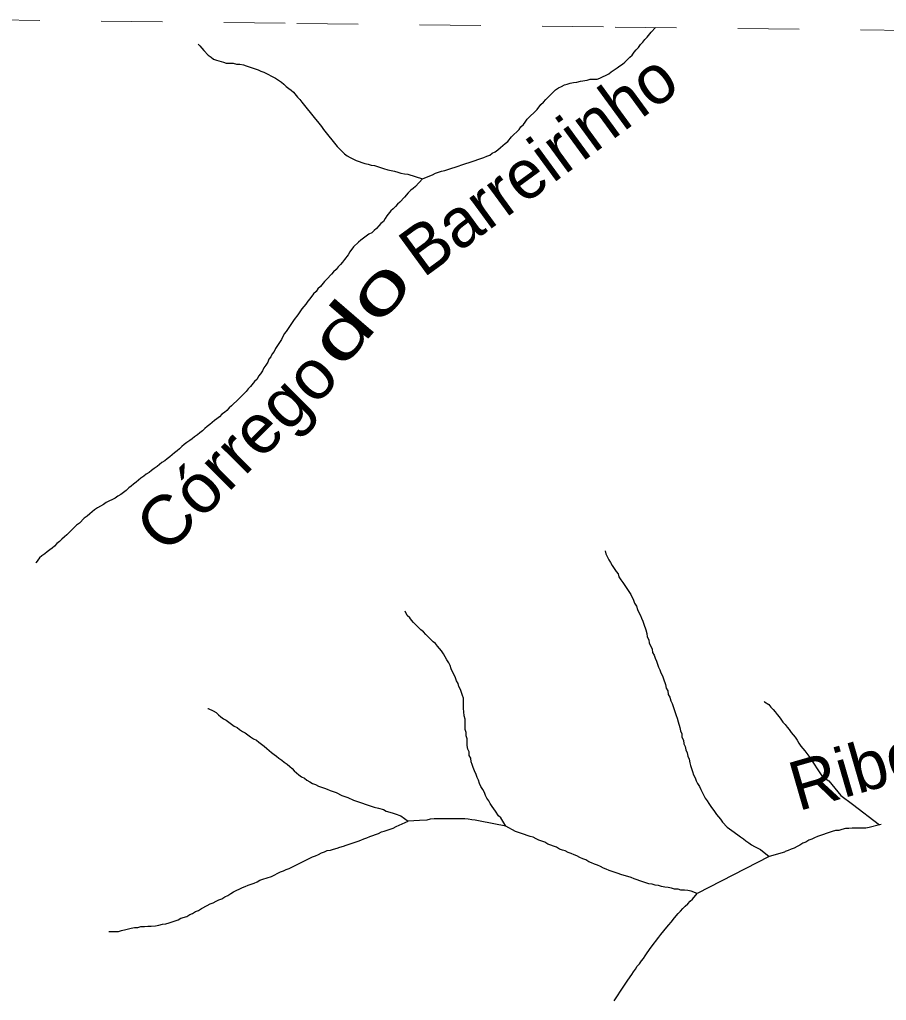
# Model space of a CAD drawing. Extents: x 652.3 to 678, y 7316.9 to 7344.9.
# Drawn here: x 666.148 to 667.562, y 7343.176 to 7344.776 of the extents above; entities that cross this region are included whole.
import ezdxf
from ezdxf.enums import TextEntityAlignment as Align

# ---------------------------------------------------------------- set-up
doc = ezdxf.new("R2010")
doc.units = 0
doc.header["$LTSCALE"] = 0.032
doc.linetypes.add('SHORT_DASHED', pattern=[2.7, 1.5, -1.2])
doc.layers.add('53', color=7, linetype='SHORT_DASHED', lineweight=13)
doc.layers.add('7', color=7, linetype='Continuous', lineweight=25)
doc.layers.add('61', color=7, linetype='Continuous')

msp = doc.modelspace()

# ---------------------------------------------------------------- linework, layer by layer
at = {"layer": '53'}
msp.add_lwpolyline([(666.0809, 7344.7756), (666.6, 7344.7695), (667.1191, 7344.7635), (667.6382, 7344.7574), (668.1573, 7344.7513), (668.6764, 7344.7452), (669.1955, 7344.7391), (669.7146, 7344.733), (670.2337, 7344.7268), (670.7528, 7344.7206), (671.2719, 7344.7144), (671.791, 7344.7082), (672.3102, 7344.702), (672.8293, 7344.6957), (673.3484, 7344.6895), (673.8675, 7344.6832), (674.3866, 7344.6769), (674.9057, 7344.6705), (675.4248, 7344.6642), (675.9439, 7344.6578), (676.4631, 7344.6514), (676.9822, 7344.645), (677.5013, 7344.6386), (678.0204, 7344.6322)], dxfattribs=at)
at = {"layer": '7'}
msp.add_line((667.5529, 7343.4632), (667.5503, 7343.4627), dxfattribs=at)
for points in [[(666.8047, 7344.5162), (666.8166, 7344.521), (666.8214, 7344.5226), (666.8262, 7344.525), (666.831, 7344.5266), (666.8357, 7344.5282), (666.8413, 7344.5298), (666.8493, 7344.5322), (666.8612, 7344.5361), (666.8708, 7344.5393), (666.8755, 7344.5409), (666.8811, 7344.5425), (666.8906, 7344.5457), (666.8954, 7344.5473), (666.905, 7344.5505), (666.9097, 7344.5528), (666.9145, 7344.5544), (666.9185, 7344.5576), (666.9233, 7344.56), (666.928, 7344.5632), (666.932, 7344.5672), (666.936, 7344.5704), (666.94, 7344.5735), (666.944, 7344.5767), (666.9503, 7344.5847), (666.9623, 7344.5966), (666.9654, 7344.6006), (666.9694, 7344.6046), (666.9726, 7344.6085), (666.9758, 7344.6133), (666.9917, 7344.6292), (666.9981, 7344.6372), (667.002, 7344.6412), (667.006, 7344.6451), (667.0219, 7344.6611), (667.0267, 7344.6642), (667.0315, 7344.6666), (667.0363, 7344.669), (667.041, 7344.6706), (667.0458, 7344.6722), (667.0514, 7344.673), (667.0569, 7344.6738), (667.0625, 7344.6754), (667.0737, 7344.677), (667.0784, 7344.6786), (667.0896, 7344.6786), (667.0943, 7344.6802), (667.1087, 7344.6873), (667.1126, 7344.6905), (667.1174, 7344.6937), (667.1222, 7344.6969), (667.127, 7344.7001), (667.1309, 7344.7032), (667.1349, 7344.7064), (667.1429, 7344.7144), (667.1469, 7344.7176), (667.15, 7344.7223), (667.1532, 7344.7263), (667.1572, 7344.7303), (667.1604, 7344.7351), (667.1644, 7344.739), (667.1675, 7344.743), (667.1715, 7344.747), (667.1779, 7344.755), (667.1851, 7344.7627)], [(666.4392, 7344.7353), (666.4419, 7344.7326), (666.4482, 7344.7255), (666.4554, 7344.7176), (666.4602, 7344.7144), (666.4642, 7344.7112), (666.4689, 7344.7096), (666.4801, 7344.7064), (666.4848, 7344.7048), (666.496, 7344.7048), (666.5016, 7344.7032), (666.5071, 7344.7032), (666.5127, 7344.7016), (666.5175, 7344.7001), (666.5222, 7344.6985), (666.5366, 7344.6937), (666.5413, 7344.6913), (666.5461, 7344.6897), (666.5652, 7344.6802), (666.57, 7344.677), (666.5748, 7344.6738), (666.5787, 7344.6706), (666.5827, 7344.6666), (666.5867, 7344.6634), (666.5907, 7344.6603), (666.5946, 7344.6571), (666.601, 7344.6491), (666.605, 7344.6451), (666.6082, 7344.6412), (666.6305, 7344.6133), (666.6336, 7344.6093), (666.64, 7344.6014), (666.6432, 7344.5966), (666.6655, 7344.5688), (666.6694, 7344.5648), (666.6774, 7344.5568), (666.6822, 7344.5536), (666.6869, 7344.5505), (666.6965, 7344.5457), (666.7108, 7344.5409), (666.7164, 7344.5401), (666.7212, 7344.5385), (666.7267, 7344.5377), (666.7363, 7344.5345), (666.7411, 7344.533), (666.7482, 7344.5306), (666.7594, 7344.5282), (666.7649, 7344.5266), (666.7697, 7344.525), (666.7753, 7344.5242), (666.7808, 7344.5234), (666.8047, 7344.5162)], [(666.8047, 7344.5162), (666.7936, 7344.5035), (666.7896, 7344.5003), (666.7856, 7344.4972), (666.7816, 7344.4932), (666.7753, 7344.486), (666.7681, 7344.4781), (666.7641, 7344.4749), (666.7609, 7344.4709), (666.757, 7344.4669), (666.753, 7344.4637), (666.7466, 7344.4558), (666.7442, 7344.451), (666.7411, 7344.4462), (666.7371, 7344.443), (666.7339, 7344.4391), (666.7299, 7344.4351), (666.7259, 7344.4319), (666.722, 7344.4279), (666.7172, 7344.4255), (666.7132, 7344.4224), (666.7084, 7344.4192), (666.7045, 7344.416), (666.7005, 7344.4128), (666.6925, 7344.4049), (666.6862, 7344.3969), (666.6838, 7344.3921), (666.6774, 7344.3842), (666.6742, 7344.3802), (666.671, 7344.3762), (666.6671, 7344.3722), (666.6639, 7344.3682), (666.6599, 7344.3643), (666.6567, 7344.3603), (666.6488, 7344.3523), (666.6448, 7344.3484), (666.6384, 7344.3404), (666.6344, 7344.3364), (666.6313, 7344.3324), (666.6273, 7344.3285), (666.6209, 7344.3205), (666.6177, 7344.3165), (666.6145, 7344.3118), (666.6114, 7344.3078)], [(666.6114, 7344.3078), (666.6082, 7344.3038), (666.605, 7344.299), (666.6018, 7344.2943), (666.5954, 7344.2863), (666.5859, 7344.272), (666.5827, 7344.2672), (666.5795, 7344.2632), (666.5748, 7344.2537), (666.5716, 7344.2489), (666.5684, 7344.2441), (666.5652, 7344.2393), (666.5628, 7344.2346), (666.5596, 7344.2306), (666.5573, 7344.2258), (666.5541, 7344.2218), (666.5525, 7344.2171), (666.5493, 7344.2123), (666.5461, 7344.2075), (666.5437, 7344.2027), (666.5405, 7344.198), (666.5374, 7344.194), (666.535, 7344.1892), (666.531, 7344.1852), (666.5246, 7344.1773), (666.5207, 7344.1733), (666.5175, 7344.1693), (666.5095, 7344.1614), (666.5055, 7344.1574), (666.4936, 7344.1455), (666.4896, 7344.1423), (666.4856, 7344.1383), (666.4817, 7344.1351), (666.4777, 7344.1319), (666.4737, 7344.128), (666.4697, 7344.1248), (666.4657, 7344.1216), (666.4618, 7344.1184), (666.4578, 7344.1152), (666.4538, 7344.112), (666.4498, 7344.1089), (666.4459, 7344.1049), (666.4419, 7344.1017), (666.4379, 7344.0985), (666.4331, 7344.0953), (666.4291, 7344.0921), (666.4252, 7344.089), (666.4204, 7344.0858), (666.4164, 7344.0826), (666.4124, 7344.0794), (666.4085, 7344.0754), (666.4045, 7344.0723), (666.4005, 7344.0691), (666.3965, 7344.0659), (666.3925, 7344.0627), (666.3886, 7344.0595), (666.3846, 7344.0563), (666.3798, 7344.0532), (666.3758, 7344.05), (666.3719, 7344.0468), (666.3671, 7344.0436), (666.3631, 7344.0404), (666.3591, 7344.0372), (666.3544, 7344.0341), (666.3504, 7344.0309), (666.3456, 7344.0277), (666.3416, 7344.0245), (666.3376, 7344.0213), (666.3337, 7344.0181), (666.3297, 7344.015), (666.3257, 7344.0118), (666.3217, 7344.0078), (666.317, 7344.0046), (666.313, 7344.0014), (666.3082, 7343.9983), (666.3034, 7343.9951), (666.2891, 7343.9879), (666.2843, 7343.9847), (666.2796, 7343.9823), (666.2748, 7343.9792), (666.27, 7343.976), (666.266, 7343.9728), (666.2621, 7343.9696), (666.2581, 7343.9656), (666.2533, 7343.9624), (666.2453, 7343.9545), (666.2406, 7343.9513), (666.2247, 7343.9354), (666.2207, 7343.9322), (666.2167, 7343.9282), (666.2127, 7343.9243), (666.2087, 7343.9211), (666.2048, 7343.9171), (666.2008, 7343.9139), (666.1968, 7343.9107), (666.1928, 7343.9075), (666.1888, 7343.9044), (666.1841, 7343.9012), (666.1801, 7343.898), (666.1745, 7343.89), (666.1743, 7343.8897)], [(667.103, 7343.9095), (667.1031, 7343.9091), (667.1039, 7343.9044), (667.1087, 7343.8948), (667.1118, 7343.89), (667.1142, 7343.8853), (667.1206, 7343.8757), (667.1238, 7343.8717), (667.1254, 7343.867), (667.1286, 7343.8622), (667.1317, 7343.8574), (667.1413, 7343.8431), (667.1445, 7343.8383), (667.1492, 7343.8288), (667.1508, 7343.824), (667.154, 7343.8192), (667.1556, 7343.8137), (667.158, 7343.8089), (667.1604, 7343.8041), (667.162, 7343.7993), (667.1644, 7343.7946), (667.166, 7343.7898), (667.1691, 7343.7802), (667.1707, 7343.7747), (667.1715, 7343.7691), (667.1739, 7343.7643), (667.1747, 7343.7588), (667.1771, 7343.754), (667.1795, 7343.7492), (667.1803, 7343.7436), (667.1827, 7343.7389), (667.1843, 7343.7341), (667.1866, 7343.7293), (667.1882, 7343.7245), (667.1898, 7343.7198), (667.1922, 7343.715), (667.1938, 7343.7102), (667.1962, 7343.7054), (667.1978, 7343.7007), (667.201, 7343.6911), (667.2026, 7343.6855), (667.2049, 7343.6808), (667.2057, 7343.6752), (667.2081, 7343.6704), (667.2097, 7343.6649), (667.2121, 7343.6601), (667.2169, 7343.6458), (667.2185, 7343.641), (667.2201, 7343.6362), (667.2217, 7343.6306), (667.2248, 7343.6211), (667.2256, 7343.6155), (667.228, 7343.6108), (667.228, 7343.6052), (667.2304, 7343.6004), (667.2312, 7343.5948), (667.2336, 7343.5901), (667.2344, 7343.5845), (667.2368, 7343.5797), (667.2376, 7343.5742), (667.24, 7343.5694), (667.2407, 7343.5638), (667.2423, 7343.559), (667.2439, 7343.5543), (667.2455, 7343.5495), (667.2471, 7343.5439), (667.2495, 7343.5391), (667.2511, 7343.5344), (667.2535, 7343.5296), (667.2567, 7343.5248), (667.259, 7343.52), (667.2662, 7343.5057), (667.2694, 7343.5017), (667.2718, 7343.497), (667.275, 7343.4922), (667.2813, 7343.4842), (667.2845, 7343.4795), (667.2909, 7343.4715), (667.2941, 7343.4667), (667.302, 7343.4588), (667.3092, 7343.4532), (667.3195, 7343.446), (667.3235, 7343.4429), (667.3283, 7343.4397), (667.3323, 7343.4365), (667.337, 7343.4333), (667.3418, 7343.4301), (667.3466, 7343.4269), (667.3561, 7343.4222), (667.3704, 7343.411)], [(666.9408, 7343.4604), (666.9328, 7343.4739), (666.9288, 7343.4771), (666.9241, 7343.485), (666.9185, 7343.4922), (666.9153, 7343.497), (666.9129, 7343.5017), (666.9097, 7343.5057), (666.9074, 7343.5105), (666.9058, 7343.5153), (666.9034, 7343.52), (666.9002, 7343.5248), (666.8978, 7343.5296), (666.8962, 7343.5352), (666.8938, 7343.5399), (666.8922, 7343.5447), (666.8899, 7343.5503), (666.8875, 7343.5559), (666.8859, 7343.5606), (666.8843, 7343.5654), (666.8835, 7343.571), (666.8811, 7343.5757), (666.8811, 7343.5813), (666.8787, 7343.5861), (666.8779, 7343.5917), (666.8779, 7343.6028), (666.8763, 7343.6076), (666.8763, 7343.6131), (666.8747, 7343.6179), (666.8747, 7343.6346), (666.8731, 7343.6402), (666.8723, 7343.6466), (666.8715, 7343.6521), (666.8715, 7343.6688), (666.87, 7343.6736), (666.8668, 7343.6832), (666.8644, 7343.6879), (666.8628, 7343.6927), (666.8604, 7343.6975), (666.8588, 7343.7023), (666.8564, 7343.707), (666.854, 7343.7118), (666.8517, 7343.7166), (666.8501, 7343.7222), (666.8477, 7343.7269), (666.8445, 7343.7317), (666.8421, 7343.7365), (666.8389, 7343.7412), (666.8357, 7343.746), (666.8294, 7343.754), (666.8262, 7343.758), (666.8222, 7343.7611), (666.8103, 7343.7731), (666.8063, 7343.7771), (666.8023, 7343.7802), (666.7904, 7343.7922), (666.7872, 7343.7961), (666.784, 7343.8001), (666.78, 7343.8041), (666.7767, 7343.8108)], [(666.455, 7343.6523), (666.4554, 7343.6521), (666.4634, 7343.6482), (666.4681, 7343.6458), (666.4721, 7343.6418), (666.4761, 7343.6386), (666.4801, 7343.6354), (666.4848, 7343.633), (666.4888, 7343.6299), (666.4936, 7343.6267), (666.4976, 7343.6235), (666.5024, 7343.6211), (666.5063, 7343.6179), (666.5111, 7343.6147), (666.5159, 7343.6123), (666.5199, 7343.6092), (666.5246, 7343.606), (666.5294, 7343.6028), (666.5342, 7343.6004), (666.5382, 7343.5972), (666.5421, 7343.594), (666.5469, 7343.5909), (666.5509, 7343.5869), (666.5549, 7343.5837), (666.5588, 7343.5805), (666.5628, 7343.5773), (666.5668, 7343.5742), (666.5708, 7343.571), (666.5756, 7343.5678), (666.5795, 7343.5646), (666.5843, 7343.5614), (666.5883, 7343.5574), (666.5923, 7343.5543), (666.5954, 7343.5503), (666.5994, 7343.5471), (666.6034, 7343.5439), (666.6074, 7343.5407), (666.6122, 7343.5383), (666.6161, 7343.5352), (666.6209, 7343.5328), (666.6257, 7343.5296), (666.6305, 7343.528), (666.6352, 7343.5256), (666.6448, 7343.5224), (666.6496, 7343.5208), (666.6543, 7343.5185), (666.6639, 7343.5153), (666.6734, 7343.5105), (666.683, 7343.5073), (666.6925, 7343.5025), (666.6973, 7343.5009), (666.7021, 7343.4994), (666.7164, 7343.4946), (666.7212, 7343.493), (666.7259, 7343.4914), (666.7331, 7343.4898), (666.7411, 7343.4874), (666.7458, 7343.485), (666.7554, 7343.4819), (666.7602, 7343.4803), (666.7697, 7343.4771), (666.7816, 7343.4683)], [(667.3622, 7343.6635), (667.3625, 7343.6633), (667.3697, 7343.6585), (667.3728, 7343.6545), (667.3768, 7343.6505), (667.38, 7343.6466), (667.3832, 7343.6426), (667.3864, 7343.6386), (667.3895, 7343.6346), (667.3927, 7343.6299), (667.3967, 7343.6259), (667.3999, 7343.6219), (667.4031, 7343.6179), (667.4063, 7343.6131), (667.4094, 7343.6092), (667.4126, 7343.6052), (667.4158, 7343.6004), (667.419, 7343.5956), (667.4222, 7343.5909), (667.4253, 7343.5869), (667.4285, 7343.5829), (667.4349, 7343.5742), (667.4572, 7343.5407), (667.4675, 7343.5344), (667.4874, 7343.5105), (667.5065, 7343.4962), (667.5503, 7343.4627)], [(666.8989, 7343.4682), (666.8962, 7343.4691), (666.8906, 7343.4699), (666.8851, 7343.4707), (666.8795, 7343.4715), (666.8739, 7343.4723), (666.8684, 7343.4723), (666.8628, 7343.4723), (666.8572, 7343.4723), (666.8517, 7343.4723), (666.8461, 7343.4723), (666.8405, 7343.4723), (666.8349, 7343.4723), (666.8294, 7343.4723), (666.8238, 7343.4723), (666.8174, 7343.4715), (666.8119, 7343.4699), (666.8001, 7343.4693)], [(666.2931, 7343.2885), (666.309, 7343.2885), (666.3138, 7343.2901), (666.3209, 7343.2917), (666.3297, 7343.2941), (666.3353, 7343.2949), (666.3408, 7343.2949), (666.3456, 7343.2965), (666.3512, 7343.2965), (666.3567, 7343.2973), (666.3623, 7343.2973), (666.3695, 7343.298), (666.375, 7343.2988), (666.3806, 7343.3004), (666.3862, 7343.3012), (666.3917, 7343.3028), (666.3965, 7343.3044), (666.4013, 7343.306), (666.4061, 7343.3076), (666.4108, 7343.31), (666.4204, 7343.3132), (666.4252, 7343.3163), (666.4299, 7343.3179), (666.4347, 7343.3211), (666.4395, 7343.3227), (666.4443, 7343.3259), (666.4538, 7343.3307), (666.4586, 7343.3339), (666.4634, 7343.3354), (666.4681, 7343.3378), (666.4729, 7343.3402), (666.4777, 7343.3418), (666.4825, 7343.345), (666.4872, 7343.3474), (666.492, 7343.3506), (666.4968, 7343.353), (666.5111, 7343.3601), (666.5159, 7343.3617), (666.5207, 7343.3641), (666.5254, 7343.3657), (666.5302, 7343.3673), (666.535, 7343.3697), (666.5397, 7343.372), (666.5445, 7343.3736), (666.5588, 7343.3784), (666.5732, 7343.3856), (666.5779, 7343.3872), (666.5827, 7343.3896), (666.5875, 7343.3911), (666.6209, 7343.4079), (666.6257, 7343.4102), (666.6305, 7343.4118), (666.6352, 7343.4142), (666.64, 7343.4166), (666.6448, 7343.4182), (666.6496, 7343.4206), (666.6551, 7343.4214), (666.6599, 7343.423), (666.6655, 7343.4246), (666.6702, 7343.4262), (666.6758, 7343.4277), (666.6806, 7343.4293), (666.6854, 7343.4309), (666.6997, 7343.4357), (666.7045, 7343.4373), (666.7092, 7343.4397), (666.714, 7343.4413), (666.7188, 7343.4437), (666.7331, 7343.4484), (666.7379, 7343.4508), (666.7426, 7343.4524), (666.757, 7343.4572), (666.7617, 7343.4596), (666.7816, 7343.4683)], [(666.8001, 7343.4693), (666.7816, 7343.4683), (666.7816, 7343.4683)], [(666.9408, 7343.4604), (666.9408, 7343.4604), (666.8989, 7343.4682)], [(667.2527, 7343.3506), (667.2431, 7343.3545), (667.2376, 7343.3553), (667.232, 7343.3561), (667.2264, 7343.3561), (667.2217, 7343.3577), (667.2161, 7343.3577), (667.2113, 7343.3593), (667.2057, 7343.3601), (667.2002, 7343.3609), (667.1946, 7343.3617), (667.1898, 7343.3633), (667.1843, 7343.3641), (667.1795, 7343.3657), (667.1739, 7343.3665), (667.1691, 7343.3681), (667.1644, 7343.3697), (667.1596, 7343.3713), (667.1548, 7343.3728), (667.15, 7343.3744), (667.1453, 7343.3768), (667.1397, 7343.3784), (667.1341, 7343.38), (667.1286, 7343.3816), (667.1238, 7343.3832), (667.119, 7343.3848), (667.1142, 7343.3864), (667.1095, 7343.388), (667.1047, 7343.3903), (667.0999, 7343.3919), (667.0951, 7343.3943), (667.0904, 7343.3967), (667.0856, 7343.3983), (667.0808, 7343.4007), (667.076, 7343.4023), (667.0713, 7343.4055), (667.0665, 7343.4071), (667.0617, 7343.4094), (667.0569, 7343.4118), (667.0522, 7343.4134), (667.0474, 7343.4158), (667.0426, 7343.4174), (667.0378, 7343.4198), (667.0331, 7343.4214), (667.0283, 7343.423), (667.0235, 7343.4262), (667.0188, 7343.4277), (667.014, 7343.4293), (667.0092, 7343.4309), (667.0044, 7343.4341), (666.9997, 7343.4357), (666.9949, 7343.4373), (666.9901, 7343.4397), (666.9853, 7343.4421), (666.9806, 7343.4437), (666.9758, 7343.4453), (666.971, 7343.4468), (666.9662, 7343.4484), (666.9615, 7343.45), (666.9567, 7343.4516), (666.9408, 7343.4604)], [(667.5503, 7343.4627), (667.5336, 7343.458), (667.528, 7343.4572), (667.5224, 7343.4572), (667.5169, 7343.4572), (667.5113, 7343.4572), (667.5057, 7343.4572), (667.5001, 7343.4564), (667.4946, 7343.4564), (667.489, 7343.4548), (667.4842, 7343.4532), (667.4787, 7343.4532), (667.4731, 7343.4516), (667.4683, 7343.45), (667.4635, 7343.4484), (667.4588, 7343.4468), (667.454, 7343.4453), (667.4492, 7343.4437), (667.4444, 7343.4413), (667.4397, 7343.4389), (667.4349, 7343.4373), (667.4301, 7343.4341), (667.4253, 7343.4325), (667.4206, 7343.4293), (667.4158, 7343.4269), (667.411, 7343.4246), (667.4063, 7343.423), (667.4015, 7343.4206), (667.3967, 7343.419), (667.3951, 7343.4177)], [(667.3951, 7343.4177), (667.3704, 7343.411), (667.3704, 7343.411), (667.2527, 7343.3506)], [(667.1174, 7343.1755), (667.1238, 7343.1851), (667.127, 7343.1898), (667.1365, 7343.2042), (667.1397, 7343.2089), (667.1461, 7343.2185), (667.1492, 7343.2225), (667.1524, 7343.2272), (667.1548, 7343.232), (667.1588, 7343.236), (667.162, 7343.2408), (667.1652, 7343.2447), (667.1683, 7343.2487), (667.1715, 7343.2535), (667.1779, 7343.263), (667.1906, 7343.279), (667.1938, 7343.2837), (667.2034, 7343.2957), (667.2065, 7343.2996), (667.2105, 7343.3036), (667.2161, 7343.3108), (667.2217, 7343.3179), (667.2256, 7343.3219), (667.2296, 7343.3259), (667.2336, 7343.3299), (667.2376, 7343.3339), (667.2415, 7343.3378), (667.2455, 7343.341), (667.2527, 7343.3506)]]:
    msp.add_lwpolyline(points, dxfattribs=at)

# ---------------------------------------------------------------- texts
at = {"layer": '61'}
for s, rotation, p in [('Barreirinho', 36.171, (667.0173, 7344.5079)), ('Ribeirão', 16.16, (667.6091, 7343.5399))]:
    msp.add_text(s, height=0.08, rotation=rotation, dxfattribs=at).set_placement(p, align=Align.CENTER)
for s, rotation, width, p in [('do', 49.214, 1.55, (666.7328, 7344.2741)), ('Córrego', 45.03, 1.05, (666.5296, 7344.0453))]:
    msp.add_text(s, height=0.08, rotation=rotation, dxfattribs=dict(at, width=width)).set_placement(p, align=Align.CENTER)

doc.saveas('drawing.dxf')
